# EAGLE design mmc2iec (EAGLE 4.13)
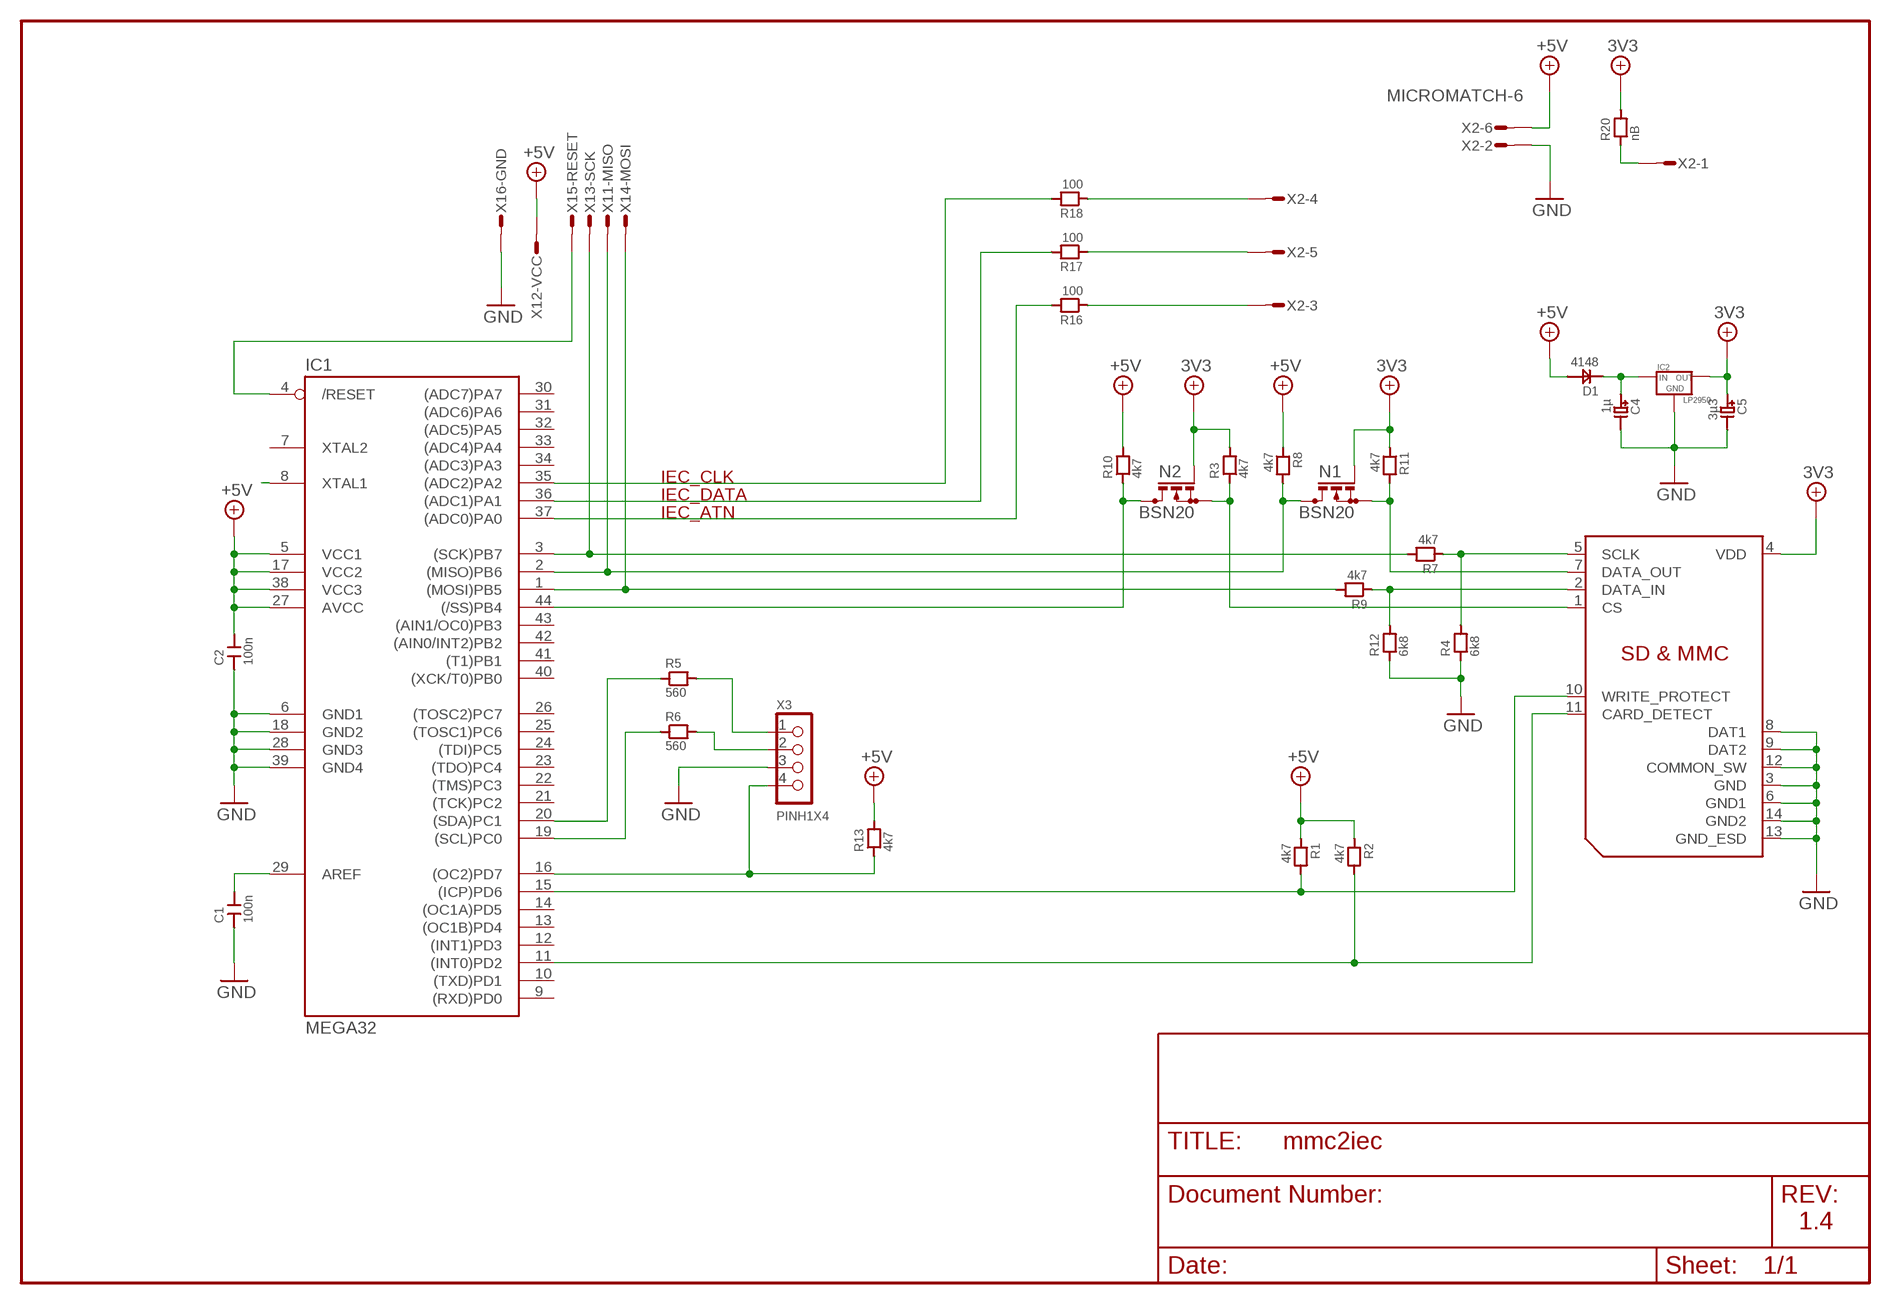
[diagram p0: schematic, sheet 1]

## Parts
C1  100n  C0805  [C0805]
C2  100n  C0805  [C0805]
C4  1µ  C_POLTA_A  [C_TANTAL_A]
C5  3µ3  C_POLTA_B  [C_TANTAL_B]
D1  4148  DSOD-123  [SOD-123]
IC1  MEGA32  MEGA16/32A  [TQFP44]
IC2  LP2950  [TO92]
N1  BSN20  SN7002  [SOT23]
N2  BSN20  SN7002  [SOT23]
R1  4k7  R0805  [R0805]
R2  4k7  R0805  [R0805]
R3  4k7  R0805  [R0805]
R4  6k8  R0805  [R0805]
R5  560  R0805  [R0805]
R6  560  R0805  [R0805]
R7  4k7  R0805  [R0805]
R8  4k7  R0805  [R0805]
R9  4k7  R0805  [R0805]
R10  4k7  R0805  [R0805]
R11  4k7  R0805  [R0805]
R12  6k8  R0805  [R0805]
R13  4k7  R0805  [R0805]
R16  100  R0805  [R0805]
R17  100  R0805  [R0805]
R18  100  R0805  [R0805]
R20  nB  R0805  [R0805]
SD1  YAMAICHI_SD_MMC2305  [FPS009-2305]
X1  AVR-ISP_1X6  [1X6_ISP]
X2  MICROMATCH-6  [MICROMATCH-6]
X3  PINH1X4  [1X4]

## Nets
3V3: C5.1 IC2.3(OUT) N1.1(G) N2.1(G) R3.2 R11.1 R20.2 SD1.4(VDD)
+5V: C2.2 D1.2 IC1.5(VCC1) IC1.17(VCC2) IC1.27(AVCC) IC1.38(VCC3) R1.1 R2.1 R8.1 R10.2 R13.2 X1.2 X2.6
/RESET: IC1.4(/RESET) X1.5
ATN: IC1.37((ADC0)PA0) R16.2
CD: IC1.11((INT0)PD2) R2.2 SD1.11(CARD_DETECT)
CLK: IC1.35((ADC2)PA2) R18.2
DATA: IC1.36((ADC1)PA1) R17.2
GND: C1.1 C2.1 C4.2 C5.2 IC1.6(GND1) IC1.18(GND2) IC1.28(GND3) IC1.39(GND4) IC2.2(GND) R4.1 R12.1 SD1.3(GND) SD1.6(GND1) SD1.8(DAT1) SD1.9(DAT2) SD1.12(COMMON_SW) SD1.13(GND_ESD) SD1.14(GND2) X1.6 X2.2 X3.3
MISO: IC1.2((MISO)PB6) N1.3(D) R8.2 X1.1
MOSI: IC1.1((MOSI)PB5) R9.2 X1.4
N$1: R20.1 X2.1
N$2: C4.1 D1.1 IC2.1(IN)
N$3: R4.2 R7.1 SD1.5(SCLK)
N$4: N1.2(S) R11.2 SD1.7(DATA_OUT)
N$5: R9.1 R12.2 SD1.2(DATA_IN)
N$6: IC1.44((/SS)PB4) N2.3(D) R10.1
N$7: R18.1 X2.4
N$8: R5.2 X3.1
N$9: R6.2 X3.2
N$10: IC1.16((OC2)PD7) R13.1 X3.4
N$11: R17.1 X2.5
N$12: R16.1 X2.3
N$13: IC1.8(XTAL1)
N$18: C1.2 IC1.29(AREF)
PC0: IC1.19((SCL)PC0) R6.1
PC1: IC1.20((SDA)PC1) R5.1
SCK: IC1.3((SCK)PB7) R7.2 X1.3
SS: N2.2(S) R3.1 SD1.1(CS)
WP: IC1.15((ICP)PD6) R1.2 SD1.10(WRITE_PROTECT)
Unconnected: IC1.7(XTAL2) IC1.9((RXD)PD0) IC1.10((TXD)PD1) IC1.12((INT1)PD3) IC1.13((OC1B)PD4) IC1.14((OC1A)PD5) IC1.21((TCK)PC2) IC1.22((TMS)PC3) IC1.23((TDO)PC4) IC1.24((TDI)PC5) IC1.25((TOSC1)PC6) IC1.26((TOSC2)PC7) IC1.30((ADC7)PA7) IC1.31((ADC6)PA6) IC1.32((ADC5)PA5) IC1.33((ADC4)PA4) IC1.34((ADC3)PA3) IC1.40((XCK/T0)PB0) IC1.41((T1)PB1) IC1.42((AIN0/INT2)PB2) IC1.43((AIN1/OC0)PB3)

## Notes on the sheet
- IEC_CLK
- IEC_DATA
- IEC_ATN
- 1.4

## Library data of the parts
C1 C2 = 0_IAV:C
C4 C5 = 0_IAV:C_POL
D1 = 0_IAV:D
IC1 = 0_IAV:MEGA16/32: MICROCONTROLLER 16 Kbytes FLASH, 512 bytes EEPROM 1 Kbytes SRAM dual UART hardware multiplier
IC2 = 0_IAV_xxx:LP2950
N1 N2 = 0_IAV:SN7002: N-CHANNEL MOS FET
R1-R13 R16-R18 R20 = 0_IAV:R
SD1 = 0_IAV_xxx:YAMAICHI_SD_MMC
X1 = 0_IAV:AVR-ISP: MicroMaTch 6 7-215464-6 / 0-215464-6 Drawing Number C-215464 DDEController.pdf
X2 = con-amp-micromatch:MICROMATCH-6: MicroMaTch 6 7-215464-6 / 0-215464-6 Drawing Number C-215464 DDEController.pdf
X3 = 0_IAV:PINH1X4

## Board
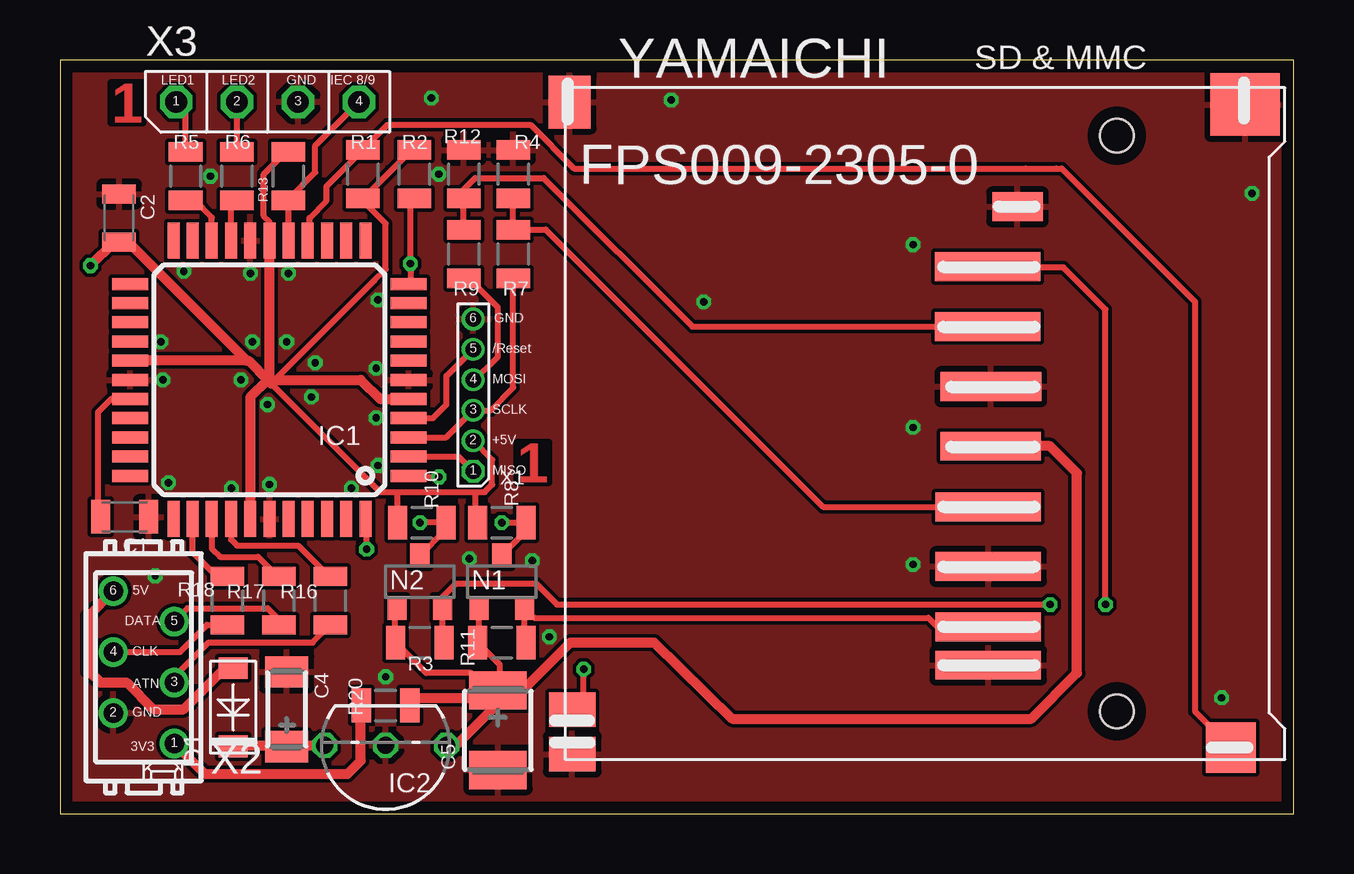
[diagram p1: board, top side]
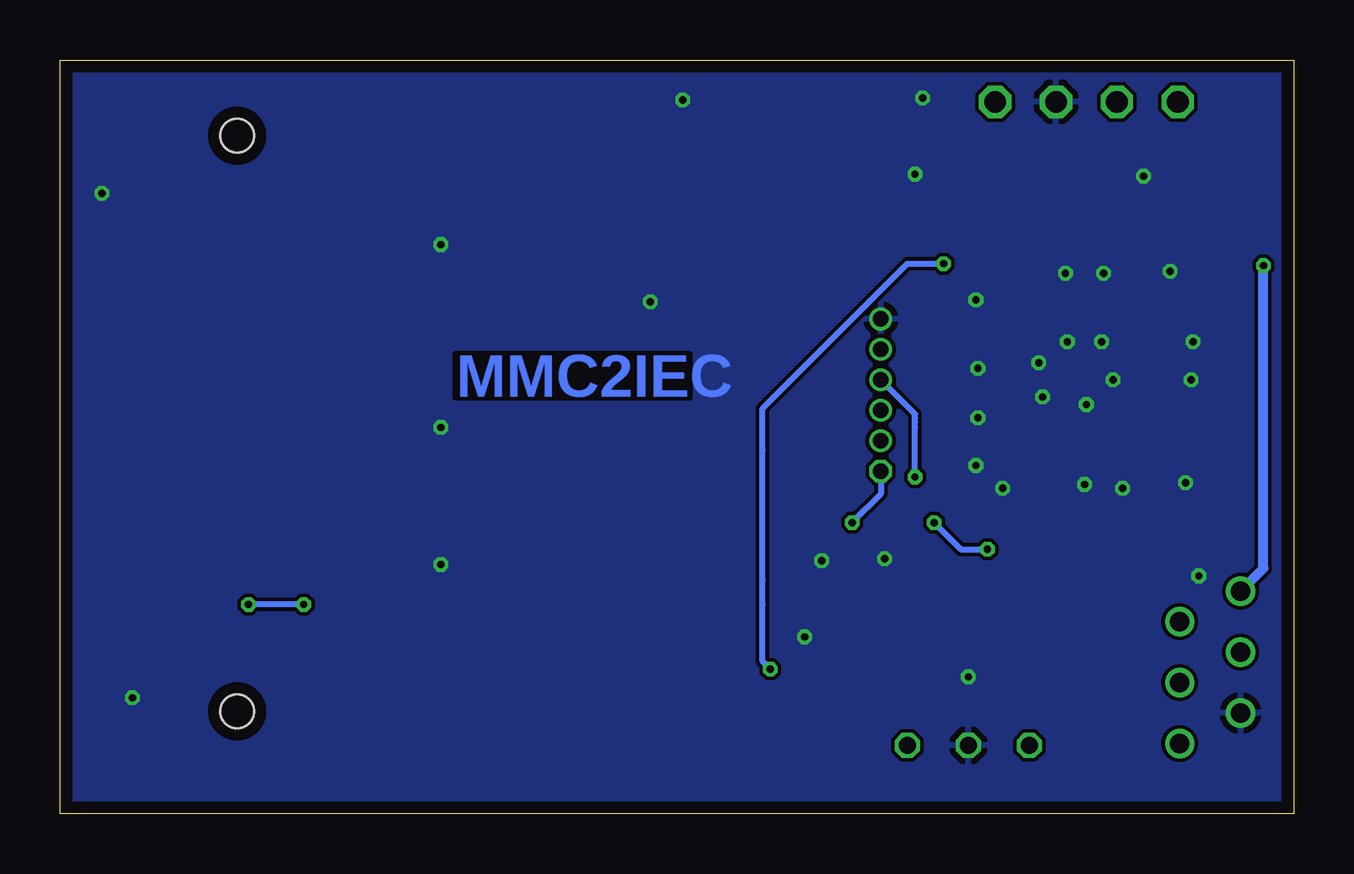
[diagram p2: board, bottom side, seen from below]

Size 51.43 x 31.43 mm. Coordinates in mm from the lower left corner, seen from the top.
Outline: 0,0 51.44,0 51.44,31.43 0,31.43 0,0
Copper layers (1*16): Top 0.035mm / dielectric 1.5mm / Bottom 0.035mm
Design rules "default": minimum track width 10mil, minimum drill 12mil, track to track 6mil, track to pad 6mil, pad to pad 6mil, via to via 6mil, smd to smd 6mil, copper to edge 20mil, drill to drill 8mil, minimum pad ring 6mil, minimum via ring 6mil, stop-mask expansion 4mil, vias tented up to drill 0mil, thermal gap 10mil

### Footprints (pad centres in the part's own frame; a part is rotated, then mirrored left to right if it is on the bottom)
C0805 = smd 0.8 x 1.4: 1 -1,0; 2 1,0
C_TANTAL_A = smd 1.3 x 1.8: 1 1.559,0; 2 -1.559,0
C_TANTAL_B = smd 1.6 x 2.4: 1 1.659,0; 2 -1.659,0
SOD-123 = smd 0.91 x 1.22: 1 -1.63,0; 2 1.63,0
TQFP44 = smd 1.5 x 0.5: 1 -5.8,4; 2 -5.8,3.2; 3 -5.8,2.4; 4 -5.8,1.6; 5 -5.8,0.8; 6 -5.8,0; 7 -5.8,-0.8; 8 -5.8,-1.6; 9 -5.8,-2.4; 10 -5.8,-3.2; 11 -5.8,-4; 23 5.8,-4; 24 5.8,-3.2; 25 5.8,-2.4; 26 5.8,-1.6; 27 5.8,-0.8; 28 5.8,0; 29 5.8,0.8; 30 5.8,1.6; 31 5.8,2.4; 32 5.8,3.2; 33 5.8,4 | smd 0.5 x 1.5: 12 -4,-5.8; 13 -3.2,-5.8; 14 -2.4,-5.8; 15 -1.6,-5.8; 16 -0.8,-5.8; 17 0,-5.8; 18 0.8,-5.8; 19 1.6,-5.8; 20 2.4,-5.8; 21 3.2,-5.8; 22 4,-5.8; 34 4,5.8; 35 3.2,5.8; 36 2.4,5.8; 37 1.6,5.8; 38 0.8,5.8; 39 0,5.8; 40 -0.8,5.8; 41 -1.6,5.8; 42 -2.4,5.8; 43 -3.2,5.8; 44 -4,5.8
TO92 = drill 0.7 octagon: 1 2.54,0; 2 0,0; 3 -2.54,0
SOT23 = smd 0.8 x 1: 1 -0.95,-1.1; 2 0.95,-1.1; 3 0,1.1
R0805 = smd 0.8 x 1.4: 1 -1.009,0; 2 1.009,0
FPS009-2305 = smd 4.4 x 1.2: 1 -5.38,6.54; 2 -5.39,4.04; 5 -5.36,-3.47; 6 -5.36,-5.96; 7 -5.36,-8.48; 8 -5.36,-10.07 | smd 4.2 x 1.2: 3 -5.25,1.54; 4 -5.26,-0.94 | smd 2.1 x 1.2: 9 -4.14,9.04 | smd 2.1 x 2.1: 10 4.75,-13.5 | smd 1.95 x 1.45: 11 -22.7,-11.92; 12 -22.7,-13.78 | smd 1.75 x 2.2: 13 -22.81,13.4 | smd 2.9 x 2.6: 14 5.35,13.3 | hole 1.4: 0,12; 0,-12
1X6_ISP = drill 0.635 pad 0.94 octagon: 1 0,0 | drill 0.635 pad 0.94 round: 2 1.27,0; 3 2.54,0; 4 3.81,0; 5 5.08,0; 6 6.35,0
MICROMATCH-6 = drill 0.813 round: 1 3.175,1.27; 2 1.905,-1.27; 3 0.635,1.27; 4 -0.635,-1.27; 5 -1.905,1.27; 6 -3.175,-1.27
1X4 = drill 0.9 octagon: 1 -3.81,0; 2 -1.27,0; 3 1.27,0; 4 3.81,0

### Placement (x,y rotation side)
C1  2.7,12.38 180 top
C2  2.46,24.84 270 top
C4  9.45,4.37 270 top
C5  18.26,3.49 90 top
D1  7.22,4.45 90 top
IC1  8.73,18.1 180 top
IC2  13.57,2.86 180 top
N1  18.42,9.68 0 top
N2  15,9.68 0 top
R1  12.62,26.67 90 top
R2  14.76,26.67 270 top
R3  15,7.14 180 top
R4  18.89,26.67 270 top
R5  5.24,26.59 90 top
R6  7.38,26.59 90 top
R7  18.89,23.34 270 top
R8  18.41,12.14 0 top
R9  16.83,23.34 270 top
R10  15.08,12.14 180 top
R11  18.42,7.14 0 top
R12  16.83,26.67 270 top
R13  9.53,26.59 90 top
R16  11.27,8.89 90 top
R17  9.13,8.89 90 top
R18  6.99,8.89 90 top
R20  13.57,4.52 0 top
SD1  44.05,16.27 0 top
X1  17.22,14.29 90 top
X2  3.49,6.11 270 top
X3  8.65,29.69 0 top

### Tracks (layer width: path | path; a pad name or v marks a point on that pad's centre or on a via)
3V3
  Top 0.254: 13.97,7.12 13.97,6.99 | 13.97,7.12 R3.2 15.26,5.87 17.15,5.87 18.1,4.92 18.41,4.92 C5.1 18.34,4.99 18.34,6.22 R11.1 17.46,7.09 | N2.1 13.97,8.5 13.97,7.12 | 17.46,7.09 17.46,6.99 | N1.1 17.46,7.09
  Top 0.305: 18.42,4.76 18.42,5.16 C5.1
  Top 0.406: SD1.4 41.26,15.33 42.39,14.21 42.39,5.87 40.48,3.97 28.02,3.97 24.77,7.14 21.27,7.14 20.96,6.83 18.97,4.84 18.42,4.84 | IC2.3 16.51,2.86 18.42,4.76 | 18.42,4.84 | 18.42,4.84 C5.1 18.42,4.91 18.42,4.84 | R20.2 14.9,4.84 18.42,4.84
+5V  (via drill 0.3)
  Top 0.254: 13.1,22.23 | 13.1,22.23 8.81,17.94 13.34,13.41 14.05,13.41 | IC1.17 | IC1.17 | IC1.17 8.73,24.69 8.49,24.92 8.49,26.67 9.45,27.62 9.47,27.6 R13.2 | R1.1 12.62,25.64 14.66,27.68 R2.1 | R1.1 12.62,25.56 | 12.54,25.64 12.6,25.64 R1.1 | 13.1,22.23 13.57,22.7 13.57,24.61 12.62,25.56 R1.1 | X1.2 18.02,14.76 18.02,13.73 17.7,13.41 17.3,13.41 | 14.05,13.41 17.3,13.41 | R10.2 14.05,12.17 14.05,13.41 | R8.1 17.3,12.25 17.3,13.41
  Top 0.406: IC1.27 7.78,18.89 | 8.73,18.02 8.81,17.94 | 8.65,18.1 8.73,18.02 | 8.65,18.1 7.86,18.89 7.78,18.89 | IC1.17 8.73,18.18 | 8.73,18.02 8.73,18.18 | IC1.38 7.93,17.38 8.65,18.1 | 8.65,18.1 8.73,18.18 | IC1.5 13.34,17.3 12.54,18.1 8.65,18.1 | D1.2 6.87,6.08 5.16,4.37 3.89,4.37 2.78,5.48 1.67,5.48 1.19,5.95 1.19,8.26 X2.6 | X2.6 | C2.2 2.25,23.84 v1.27,22.86 | C2.2 2.46,23.81 2.86,23.81 7.78,18.89 | C2.2 | 7.78,18.89
  Bottom 0.406: X2.6 | v1.27,22.86 1.27,10.24 X2.6
/RESET
  Top 0.254: IC1.4 15.55,16.5 16.11,17.07 16.11,18.26 X1.5 | X1.5
ATN
  Top 0.254: IC1.37 7.13,11.44 7.38,11.19 9.92,11.19 11.27,9.84 R16.2
CD  (via drill 0.3)
  Top 0.254: SD1.11 21.83,4.29 v21.83,6.03 | 14.76,25.64 | 14.76,25.64 R2.2 | 14.76,25.64 14.61,25.48 v14.61,22.94 14.61,22.15 14.58,22.15 IC1.11
  Bottom 0.254: v21.83,6.03 22.15,6.35 22.15,8.73 22.15,9.76 22.15,15.16 22.15,16.91 16.11,22.94 v14.61,22.94
CLK
  Top 0.254: R18.2 6.53,9.9 5.53,10.9 IC1.35
DATA
  Top 0.254: IC1.36 6.33,11.05 6.67,10.72 8.26,10.72 9.13,9.84 R17.2
GND  (via drill 0.3)
  other vias: 25.48,29.77 9.53,22.54 13.18,18.57 13.18,16.51 7.94,22.54 4.29,18.1 7.54,18.1 13.26,21.43 12.14,13.57 8.73,13.73 7.14,13.57 4.52,13.81 35.56,10.4 35.56,16.11 35.56,23.73 49.69,25.88 9.45,19.69 8.02,19.69 4.21,19.69 5.16,22.62 10.64,18.81 8.65,17.07 10.48,17.38 13.26,14.53 48.42,4.84 19.68,10.56 17.07,10.64 13.57,5.72 20.4,7.38 15.8,26.67 26.83,21.35 15.48,29.85 6.27,26.59 3.97,9.92
  pour Top: 0,0 0,31.43 51.44,31.43 51.44,0
  pour Bottom: 0,0 0,31.43 51.44,31.43 51.44,0
MISO  (via drill 0.3)
  Top 0.254: v18.42,12.14 R8.2 19.45,12.14 19.45,11.82 N1.3 | v18.42,12.14 | X1.1 | IC1.2 16.61,14.9 X1.1
  Bottom 0.254: X1.1 | v18.42,12.14 17.22,13.34 X1.1
MOSI  (via drill 0.3)
  Top 0.254: IC1.1 14.58,14.05 v15.8,14.05 | R9.2 17.04,22.33 18.26,21.11 18.26,19.05 17.22,18.02 | 17.22,18.02 | X1.4 17.22,18.02
  Bottom 0.254: X1.4 15.8,16.67 15.8,16.51 15.8,16.35 15.8,16.11 v15.8,14.05
N$1
  Top 0.406: X2.1 6.03,1.67 11.99,1.67 12.54,2.22 12.54,4.52 R20.1
N$2
  Top 0.406: D1.1 7.27,2.86 9.4,2.86 C4.1 9.5,2.86 IC2.1
N$3
  Top 0.254: SD1.5 31.81,12.8 20.24,24.37 18.89,24.37 | 18.89,24.37 18.81,24.45 | 18.89,24.37 | R7.1 18.89,24.37 | 18.89,24.37 R4.2 | 18.89,24.37
N$4
  Top 0.254: 38.71,7.78 38.74,7.78 | 38.71,7.78 SD1.7 | 38.71,7.78 36.59,7.78 36.2,8.18 19.76,8.18 N1.2 19.37,7.2 R11.2
N$5
  Top 0.254: R9.1 16.83,24.19 16.83,25.82 R12.2 16.83,26.04 | SD1.2 26.36,20.31 20.16,26.51 17.3,26.51 16.83,26.04 | 16.83,26.04
N$6  (via drill 0.3)
  Top 0.254: v15,12.14 R10.1 16.03,12.14 16.03,11.82 N2.3 | v15,12.14 | IC1.44 12.73,12.35 12.78,12.38 v12.78,11.03
  Bottom 0.254: v15,12.14 13.89,11.03 v12.78,11.03
N$7
  Top 0.254: R18.1 6.14,7.88 5,6.75 X2.4 | X2.4
N$8
  Top 0.254: R5.2 5.24,29.29 X3.1
N$9
  Top 0.254: R6.2 X3.2
N$10
  Top 0.254: IC1.16 9.53,25.55 9.53,25.56 R13.1 9.53,25.64 10.64,26.75 10.64,27.86 X3.4
N$11
  Top 0.254: X2.5 5.32,8.57 8.65,8.57 9.13,8.1 R17.1 | R17.1
N$12
  Top 0.254: R16.1 10.53,7.14 6.19,7.14 4.76,5.72 X2.3 | X2.3
N$18
  Top 0.254: IC1.29 2.14,17.3 1.59,16.75 1.59,12.62 1.59,12.46 C1.2
PC0
  Top 0.254: R6.1 7.33,25.58 7.13,25.39 IC1.19
PC1
  Top 0.254: R5.1 5.61,25.58 6.33,24.86 IC1.20
SCK
  Top 0.254: X1.3 | IC1.3 16.09,15.7 X1.3 | X1.3 17.94,16.83 18.89,17.78 18.89,22.3 18.89,22.31 R7.2
SS  (via drill 0.3)
  Top 0.254: v41.28,8.73 20.72,8.73 19.84,9.6 18.89,9.6 16.51,9.6 15.95,9.05 N2.2 15.95,7.2 R3.1 | v43.58,8.73 43.58,21.03 41.83,22.78 38.58,22.78 38.61,22.81 SD1.1
  Bottom 0.254: v41.28,8.73 v43.58,8.73
WP
  Top 0.254: SD1.10 48.8,2.79 47.31,4.29 47.31,21.35 41.75,26.91 41.51,26.91 40.24,26.91 21.43,26.91 19.61,28.73 13.65,28.73 12.62,27.7 R1.2 11.11,26.17 11.11,25.56 10.4,24.84 10.4,23.96 IC1.15

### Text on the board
Top: 1 | 1
Bottom: MMC2IEC
tPlace: LED1 | 1 | LED2 | 2 | GND | 3 | IEC 8/9 | 4 | 6 | GND | 5 | /Reset | 4 | MOSI | 3 | SCLK | 2 | +5V | 1 | MISO | 6 | 5V | DATA | 5 | 4 | CLK | ATN | 3 | 2 | GND | 3V3 | 1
